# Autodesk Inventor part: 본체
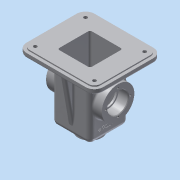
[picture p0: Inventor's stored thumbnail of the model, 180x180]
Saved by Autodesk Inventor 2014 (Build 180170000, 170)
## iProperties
Created: 2015-12
Part Number: 본체
Material: 알루미늄 6061
Document SubType Name: Modeling
Designer: Administrator
Density: 2.71 g/cm^3
Appearance: 알루미늄 - 평지
Mass: 854.215 g
Surface Area: 937.334 cm^2
Volume: 315.208 cm^3
Author: Administrator
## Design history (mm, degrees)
sketch "스케치1"
  geometry: L1 (32.5, 32.5)-(-32.5, 32.5); L2 (-32.5, 32.5)-(-32.5, -32.5); L3 (-32.5, -32.5)-(32.5, -32.5); L4 (32.5, -32.5)-(32.5, 32.5); L5 (32.5, 32.5)-(-32.5, -32.5); L6 (-32.5, 32.5)-(32.5, -32.5); 1 further point
  constraints: 12 end point, 2 midpoint, 2 parallel, 1 horizontal, 1 perpendicular
  dimensions: "d0" = 65 distance of L3.end L2.end; "d1" = 65 distance of L2.end L1.end
extrude "돌출1" new body sketch "스케치1" stored distance "d2" = 110; taper "d3" = 0 deg
sketch "스케치2"
  geometry: C1 r 20 at (0, 0); 1 further point
  constraints: 1 centre point, 1 coincident
  dimensions: "d4" = 40 diameter of C1
extrude "돌출2" join sketch "스케치2" distance "d5" = 10; taper "d6" = 0 deg
sketch "스케치5"
  geometry: C1 r 27.5 at (0, 0); 1 further point
  constraints: 1 centre point, 1 coincident
  dimensions: "d15" = 55 diameter of C1
extrude "돌출5" join sketch "스케치5" stored distance "d16" = 95; taper "d17" = 0 deg
sketch "스케치6"
  geometry: C1 r 27.5 at (0, 0) reference; C2 r 17.5 at (0, 0)
  constraints: 1 centre point, 1 coincident
  dimensions: "d18" = 35 diameter of C2
extrude "돌출6" cut sketch "스케치6" distance "d19" = 17; taper "d20" = 0 deg
sketch "스케치7"
  geometry: C1 r 27.5 at (0, 0) reference; C2 r 17.5 at (0, 0)
  constraints: 1 centre point, 1 coincident
  dimensions: "d21" = 35 diameter of C2
extrude "돌출7" cut sketch "스케치7" distance "d22" = 17; taper "d23" = 0 deg
sketch "스케치9"
  geometry: C1 r 20 at (0, 0) reference; C2 r 10.5 at (0, 0)
  constraints: 1 centre point, 1 coincident
  dimensions: "d28" = 21 diameter of C2
extrude "돌출9" cut sketch "스케치9" distance "d29" = 15; taper "d30" = 0 deg
sketch "스케치11"
  geometry: L1 (32.5, 32.5)-(-32.5, 32.5) reference; L2 (-32.5, 32.5)-(-32.5, -32.5) reference; L3 (-32.5, -32.5)-(32.5, -32.5) reference; L4 (32.5, -32.5)-(32.5, 32.5) reference; L5 (-60, -52.5)-(60, -52.5); L6 (60, -52.5)-(60, 52.5); L7 (60, 52.5)-(-60, 52.5); L8 (-60, 52.5)-(-60, -52.5); L9 (-60, -52.5)-(60, 52.5); L10 (60, -52.5)-(-60, 52.5); 1 further point
  constraints: 12 end point, 2 midpoint, 2 parallel, 1 horizontal, 1 perpendicular
  dimensions: "d31" = 120 distance of L7.end L6.end; "d32" = 105 distance of L6.end L5.end
extrude "돌출10" join sketch "스케치11" distance "d33" = 2; taper "d34" = 0 deg
sketch "스케치12"
  geometry: L1 (32.5, -32.5)-(32.5, 32.5) reference; L2 (-32.5, -32.5)-(32.5, -32.5) reference; L3 (-32.5, 32.5)-(-32.5, -32.5) reference; L4 (32.5, 32.5)-(-32.5, 32.5) reference; L5 (-65, -57.5)-(65, -57.5); L6 (65, -57.5)-(65, 57.5); L7 (65, 57.5)-(-65, 57.5); L8 (-65, 57.5)-(-65, -57.5); L9 (-65, -57.5)-(65, 57.5); L10 (65, -57.5)-(-65, 57.5); 1 further point
  constraints: 12 end point, 2 midpoint, 2 parallel, 1 horizontal, 1 perpendicular
  dimensions: "d35" = 130 distance of L7.end L6.end; "d36" = 115 distance of L6.end L5.end
extrude "돌출11" join sketch "스케치12" distance "d37" = 8; taper "d38" = 0 deg
sketch "스케치13"
  geometry: L1 (-27.5, -27.5)-(27.5, -27.5); L2 (27.5, -27.5)-(27.5, 27.5); L3 (27.5, 27.5)-(-27.5, 27.5); L4 (-27.5, 27.5)-(-27.5, -27.5); L5 (-27.5, -27.5)-(27.5, 27.5); L6 (27.5, -27.5)-(-27.5, 27.5); 1 further point
  constraints: 12 end point, 2 midpoint, 2 parallel, 1 horizontal, 1 perpendicular
  dimensions: "d39" = 55 distance of L3.end L2.end; "d40" = 55 distance of L2.end L1.end
extrude "돌출12" cut sketch "스케치13" distance "d41" = 105; taper "d42" = 0 deg
sketch "스케치14"
  geometry: L1 (-100, 90)-(-100, -25) reference; L2 (-108, 90)-(-108, -25) reference; L3 (-110, -20)-(-110, 85) reference; L4 (-100, 32.5)-(-100, 29.5); L5 (-100, 29.5)-(-82.336, 29.5); L6 (-100, 32.5)-(-100, 35.5); L7 (-100, 35.5)-(-82.336, 35.5); C1 r 27.5 at (-55, 32.5) reference; A1 r 27.5 centre (-55, 32.5) between (-82.336, 29.5) and (-82.336, 35.5) reference; A2 r 27.5 centre (-55, 32.5) between (-82.336, 35.5) and (-82.336, 29.5)
  constraints: 8 end point, 4 point on circle, 2 perpendicular, 2 point on line, 1 centre point, 1 coincident, 1 midpoint
  dimensions: "d43" = 3 distance of L4.start L4.end; "d44" = 3 distance of L4.start L6.end
extrude "돌출13" join sketch "스케치14" distance "d45" = 10; taper "d46" = 0 deg
sketch "스케치15"
  geometry: L1 (-57.5, 45)-(57.5, 45) reference; L2 (-32.5, -55)-(-32.5, 45) reference; L3 (32.5, -55)-(32.5, 45) reference; L4 (-57.5, 45)-(-47.5, 45); L5 (-47.5, 45)-(-32.5, -40.069); L6 (-32.5, -40.069)-(-32.5, 45); 1 further point
  constraints: 6 end point, 2 point on line, 1 collinear
  dimensions: "d47" = 10 distance of L1.start L4.end; "d48" = 100 deg angle of L4 L5
extrude "돌출14" join sketch "스케치15" stored distance "d49" = 10; taper "d50" = 0 deg
sketch "스케치16"
  geometry: L1 (-50, -42.5)-(50, -42.5); L2 (50, -42.5)-(50, 42.5); L3 (50, 42.5)-(-50, 42.5); L4 (-50, 42.5)-(-50, -42.5); L5 (-50, -42.5)-(50, 42.5); L6 (50, -42.5)-(-50, 42.5); C1 r 7.5 at (-50, 42.5); C2 r 7.5 at (50, 42.5); C3 r 7.5 at (50, -42.5); C4 r 7.5 at (-50, -42.5); 1 further point
  constraints: 12 end point, 4 centre point, 4 coincident, 2 midpoint, 2 parallel, 1 horizontal, 1 perpendicular
  dimensions: "d51" = 100 distance of L3.end L2.end; "d52" = 85 distance of L2.end L1.end; "d53" = 15 diameter of C1; "d54" = 15 diameter of C2; "d55" = 15 diameter of C3; "d56" = 15 diameter of C4
extrude "돌출15" join sketch "스케치16" distance "d57" = 3; taper "d58" = 0 deg
sketch "스케치17"
  geometry: C1 r 7.5 at (0, 0) reference; C2 r 3 at (0, 0); 1 further point
  constraints: 1 centre point, 1 coincident
  dimensions: "d59" = 6 diameter of C2
extrude "돌출16" cut sketch "스케치17" distance "d60" = 13; taper "d61" = 0 deg
sketch "스케치18"
  geometry: C1 r 7.5 at (0, 0) reference; C2 r 3 at (0, 0); 1 further point
  constraints: 1 centre point, 1 coincident
  dimensions: "d62" = 6 diameter of C2
extrude "돌출17" cut sketch "스케치18" distance "d63" = 13; taper "d64" = 0 deg
sketch "스케치19"
  geometry: C1 r 7.5 at (0, 0) reference; C2 r 3 at (0, 0); 1 further point
  constraints: 1 centre point, 1 coincident
  dimensions: "d65" = 6 diameter of C2
extrude "돌출18" cut sketch "스케치19" distance "d66" = 13; taper "d67" = 0 deg
sketch "스케치20"
  geometry: C1 r 7.5 at (0, 0) reference; C2 r 3 at (0, 0); 1 further point
  constraints: 1 centre point, 1 coincident
  dimensions: "d68" = 6 diameter of C2
extrude "돌출19" cut sketch "스케치20" distance "d69" = 13; taper "d70" = 0 deg
sketch "스케치21"
  geometry: C1 r 17.5 at (0, 0) reference; C2 r 15 at (0, 0)
  constraints: 1 centre point, 1 coincident
  dimensions: "d71" = 30 diameter of C2
extrude "돌출20" cut sketch "스케치21" distance "d72" = 100; taper "d73" = 0 deg
sketch "스케치22" dims "d74" = 42
  geometry: C1 r 27.5 at (0, 0) reference; 2 further points
  constraints: 1 coincident, 1 horizontal alignment, 2 other
hole "구멍1" sketch "스케치22" at (-21, 0) diameter "d75" = 3.242; stored, may be unused: countersink angle "d79" = 90 deg, drill point angle "d81" = 118 deg; dims "d76" = 8, "d77" = 4, "d78" = 2, "d80" = 10
sketch "스케치23" dims "d85" = 29
  geometry: C1 r 20 at (0, 0) reference; 2 further points
  constraints: 1 coincident, 1 vertical alignment, 2 other
hole "구멍2" sketch "스케치23" at (0, 14.5) diameter "d86" = 2.459; stored, may be unused: countersink angle "d90" = 90 deg, drill point angle "d92" = 118 deg; dims "d87" = 7, "d88" = 4, "d89" = 2, "d91" = 9
sketch "스케치24"
  geometry: L1 (0, 65)-(0, 0) reference; L2 (0, 65)-(0, 32.5); L3 (10, 12.5)-(10, 52.5) reference; L4 (10, 32.5)-(-16, 32.5); 1 further point
  constraints: 4 end point, 2 midpoint, 1 coincident, 1 perpendicular, 1 other
  dimensions: "d96" = 32.5 distance of L1.start L2.end; "d97" = 26 distance of L4.start L4.end
feature "엠보싱1" sketch "스케치24" dims "d98" = 0.5, "d99" = 0
fillet "모깎기1" dims "d100" = 3
fillet "모깎기2" dims "d101" = 15
fillet "모깎기3" dims "d102" = 8
fillet "모깎기4" dims "d103" = 3
fillet "모깎기5" dims "d104" = 8
fillet "모깎기6" dims "d105" = 3
fillet "모깎기7" dims "d106" = 3
fillet "모깎기8" dims "d107" = 10
fillet "모깎기9" dims "d108" = 3
chamfer "모따기1" distance "d109" = 1; stored, may be unused: second distance "d110" = 2, angle "d111" = 45 deg
fillet "모깎기10" dims "d112" = 0.3
fillet "모깎기11" dims "d113" = 1
fillet "모깎기12" dims "d114" = 3
node "솔리드1"
mirror "대칭1"
mirror "대칭2"
pattern_circular "원형 패턴1" dims angle "d83" = 360 deg
mirror "대칭3"
pattern_circular "원형 패턴2" dims angle "d94" = 360 deg
